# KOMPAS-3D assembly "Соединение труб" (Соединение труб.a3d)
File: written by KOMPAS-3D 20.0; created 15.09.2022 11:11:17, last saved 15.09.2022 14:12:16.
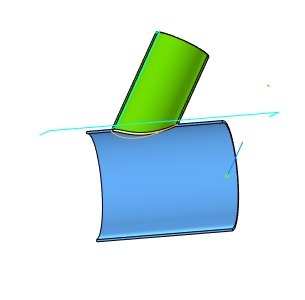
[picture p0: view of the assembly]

Document properties: Полное имя файла: D:\YAKOVLEV\ПРОЕКТЫ\ДЦ-2. ДП-7 Газопровод Окожушивание\ПРОБА Соединение труб. Окожушивание\Соединение труб.a3d

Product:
- Part/product: Соединение труб
    Масса: 5828.65
  - unknown [Обозначение сварного шва]: Обозначение стандартного шва по ГОСТ
      additional columns: 0; 1; 1; 3.66437; 3.66437; 0.282403; 1; Длина, сечение шва и плотность наплавленного материала
  - Component [detail]: Труба  | Материал: Сталь 45  ГОСТ 1050-2013 (density 7810 kg/m3); Масса: 4519.05; source file: Труба.m3d
  - Component [detail]: Вставка  | Материал: Сталь 45  ГОСТ 1050-2013 (density 7810 kg/m3); Масса: 1309.6; source file: Вставка.m3d

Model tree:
1. Введите текст обозначения...  (labels: {F8D7F836-C962-4DAC-9A52-ED5B9D430847})
2. Обозначение стандартного шва по ГОСТ:1  (with: Обечайка:1)  (labels: {B79062AB-18CA-4C2C-A874-8D817D118EDE}; Обозначение стандартного шва по ГОСТ; OBJ2D_HIDDEN; {B8F93724-DA15-4186-B3D0-1CAD93540E6C})
     Длина линии сварного шва = 3664.37; Длина сварного шва = 3664.37; Масса* наплавленного материала = 0.282403
3. Смещенная плоскость:1
     Расстояние = 1800; Ориентация = 2; Ориентация = 2

Referenced files in D:\YAKOVLEV\ПРОЕКТЫ\ДЦ-2. ДП-7 Газопровод Окожушивание\ПРОБА Соединение труб. Окожушивание\: Труба.m3d, Вставка.m3d
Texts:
  Welding3DConfiguration
  Точка начала. Х
  Точка начала. Y
  Точка начала. Z
  Обозначения сварных швов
